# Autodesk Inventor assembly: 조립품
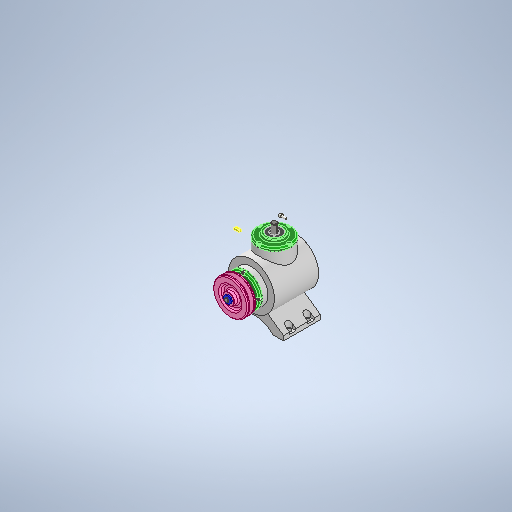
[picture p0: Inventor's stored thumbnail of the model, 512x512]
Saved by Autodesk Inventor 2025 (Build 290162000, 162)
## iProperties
Created: 2024-07
Part Number: 조립품
Document SubType Name: Assembly
Designer: SAMSUNG
Author: SAMSUNG
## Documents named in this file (15)
- C:\Users\SAMSUNG\Desktop\740709V1006\조립품.iam
- C:\Users\SAMSUNG\Desktop\740709V1006\본체.ipt
- C:\Users\SAMSUNG\Desktop\740709V1006\V-벨트풀리\V-벨트풀리.ipt
- C:\Users\SAMSUNG\Desktop\740709V1006\메인 베벨기어\메인 베벨기어.ipt
- C:\Users\SAMSUNG\Desktop\740709V1006\메인 축\메인 축.ipt
- C:\Users\SAMSUNG\Desktop\740709V1006\베어링 6203\베어링 6203.ipt
- C:\Users\SAMSUNG\Desktop\740709V1006\볼트 M4 x 10\볼트 M4 x 10.ipt
- C:\Users\SAMSUNG\Desktop\740709V1006\서브 베벨기어\서브 베벨기어.ipt
- C:\Users\SAMSUNG\Desktop\740709V1006\서브 축\서브 축.ipt
- C:\Users\SAMSUNG\Desktop\740709V1006\오일실 17 x 32 x 8\오일실 17 x 32 x 8.ipt
- C:\Users\SAMSUNG\Desktop\740709V1006\와셔 4 x 16\와셔 4 x 16.ipt
- C:\Users\SAMSUNG\Desktop\740709V1006\육각볼트 M4 x 8\육각볼트 M4 x 8.ipt
- C:\Users\SAMSUNG\Desktop\740709V1006\커버\커버.ipt
- C:\Users\SAMSUNG\Desktop\740709V1006\키 4 x 4 x 14\키 4 x 4 x 14.ipt
- C:\Users\SAMSUNG\Desktop\740709V1006\키 5 x 5 x 14\키 5 x 5 x 14.ipt
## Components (1 placed, 1 different names)
1. V-벨트풀리:2
